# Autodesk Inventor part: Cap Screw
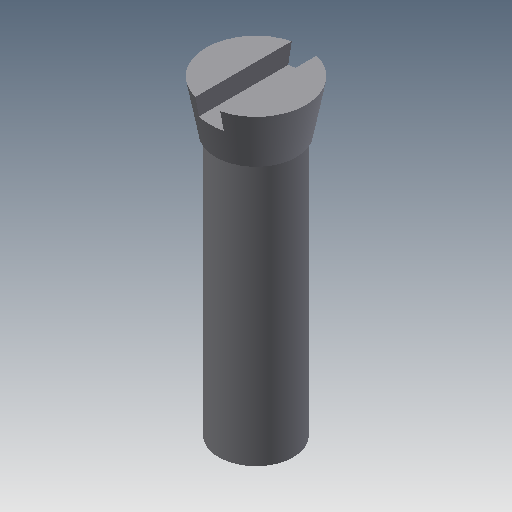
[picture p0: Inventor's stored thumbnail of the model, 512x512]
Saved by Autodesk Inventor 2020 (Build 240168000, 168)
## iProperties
Created: 2002-02
Part Number: Cap Screw
Document SubType Name: Modeling
Designer: ***
Density: 1 g/cm^3
Material: Generic
Appearance: Default
Control State: 0
Master: False
Checked Out: False
Shininess: 77.0
Length Units: 11269
Angle Units: 11279
Time Units: 11290
Mass Units: 11283
Length Display Precision: 3
Angle Display Precision: 2
Density: 0.0
Volumn: 0.0
Area: 0.0
PropertySet Name: Model Information
Author: ***
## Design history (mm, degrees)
sketch "Sketch1"
  geometry: L1 (0, 27.83)-(4, 27.83); L2 (4, 27.83)-(3.25, 23.83); L3 (3.25, 23.83)-(0, 23.83); L4 (0, 23.83)-(0, 27.83)
  constraints: 8 end point, 1 horizontal, 1 parallel, 1 perpendicular, 1 point on line
  dimensions: "d2" = 4 distance from line of L1 L2.end; "d5" = 8 diameter of L1.end L4; "d6" = 6.5 diameter of L3.start L4; "d14" = 4 distance of L3.end L1.start
revolve "Revolution1" sketch "Sketch1" stored, may be unused: angle "d7" = 90 deg
sketch "Sketch2"
  geometry: C1 r 3 at (0, 0)
  constraints: 1 centre point
  dimensions: "d8" = 6 diameter of C1
extrude "Extrusion1" join sketch "Sketch2" distance "d9" = 21; taper "d10" = 0 deg
sketch "Sketch3"
  geometry: L1 (-1, 28.967)-(1, 28.967); L2 (1, 28.967)-(1, 26.33); L3 (1, 26.33)-(-1, 26.33); L4 (-1, 26.33)-(-1, 28.967); L5 (-4, 27.83)-(4, 27.83) reference
  constraints: 8 end point, 2 parallel, 1 horizontal, 1 perpendicular
  dimensions: "d11" = 2 distance of L1.start L1.end; "d15" = 1.5 distance between parallel lines of L5 L3
extrude "Extrusion2" cut sketch "Sketch3" extent not by distance; stored distance "d12" = 24; taper "d13" = 0 deg
body "Solid1"
